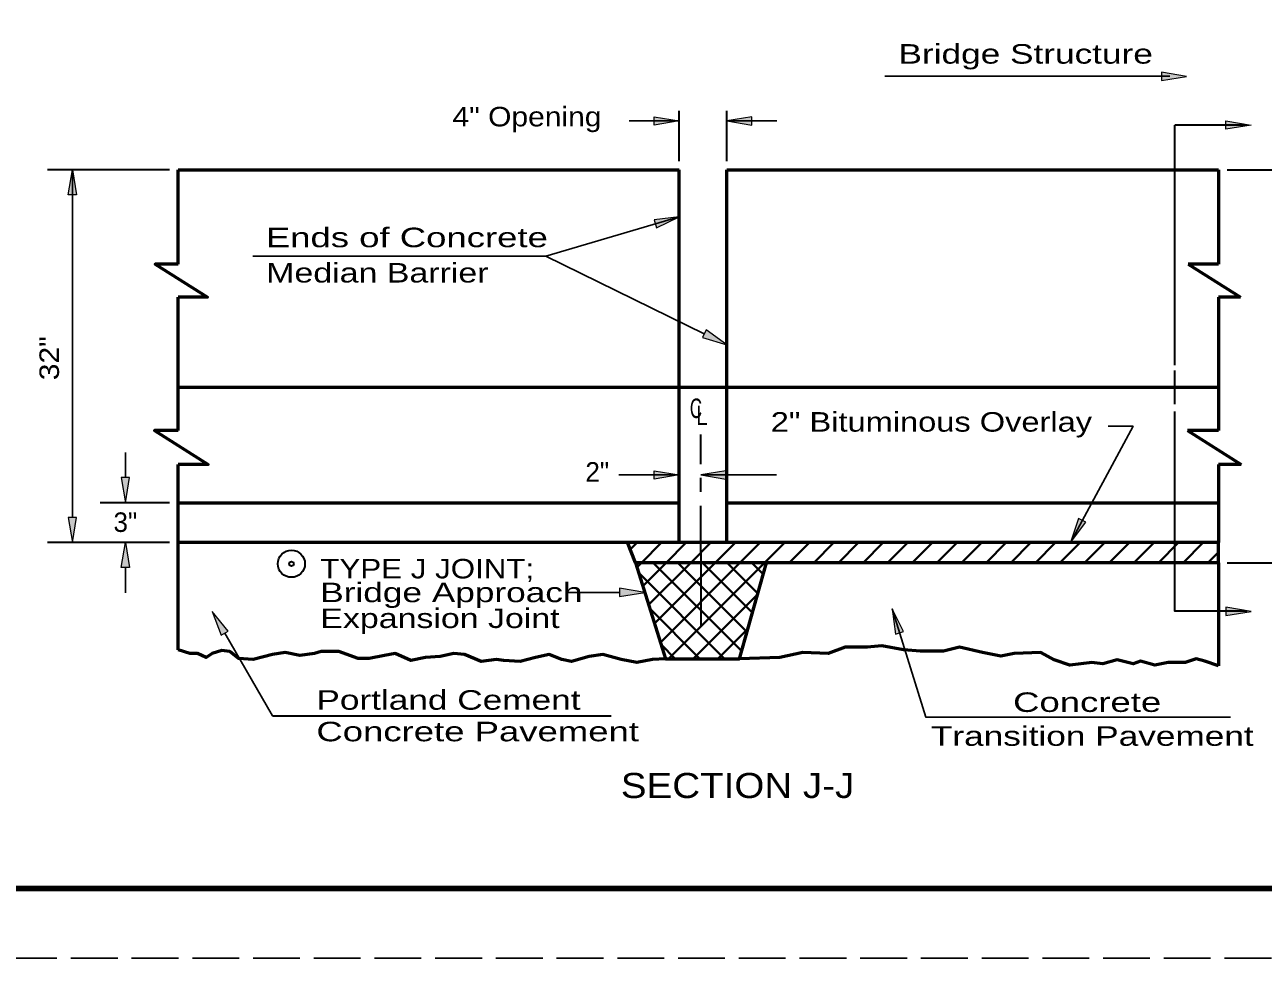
# Model space of a CAD drawing. Extents: x 14 to 49.3, y 28 to 50.
# Drawn here: x 31.51 to 40.4, y 28.04 to 34.74 of the extents above; entities that cross this region are included whole.
import ezdxf

# ---------------------------------------------------------------- set-up
doc = ezdxf.new("R2010")
doc.units = 0
doc.header["$LTSCALE"] = 0.056
doc.linetypes.add('LONG_DASH_SHORT_DASH', pattern=[9.9, 6, -1.2, 1.5, -1.2])
doc.linetypes.add('LONG_DASHED', pattern=[7.5, 6, -1.5])
for name, color, linetype, lineweight in [('1', 7, 'Continuous', 35), ('3', 7, 'Continuous', 13), ('5', 7, 'Continuous', 35), ('6', 7, 'Continuous', 13), ('7', 7, 'LONG_DASH_SHORT_DASH', 35)]:
    doc.layers.add(name, color=color, linetype=linetype, lineweight=lineweight)

msp = doc.modelspace()

# ---------------------------------------------------------------- hatches: boundary and pattern name
at = {"layer": '1'}
for points in [[(36.02508, 34.02208), (36.02508, 34.08208), (36.20508, 34.05208), (36.20508, 34.05208)], [(36.72583, 34.02208), (36.72583, 34.08208), (36.54583, 34.05208), (36.54583, 34.05208)], [(40.13058, 33.99175), (40.13058, 34.05175), (40.31058, 34.02175), (40.31058, 34.02175)], [(31.87767, 33.52033), (31.81767, 33.52033), (31.84767, 33.70033), (31.84767, 33.70033)], [(32.25767, 31.49233), (32.19767, 31.49233), (32.22767, 31.31233), (32.22767, 31.31233)], [(36.02508, 31.482), (36.02508, 31.542), (36.20508, 31.512), (36.20508, 31.512)], [(36.53942, 31.482), (36.53942, 31.542), (36.3595, 31.512), (36.3595, 31.512)], [(31.87767, 31.20633), (31.81767, 31.20633), (31.84767, 31.02633), (31.84767, 31.02633)], [(32.25767, 30.84633), (32.19767, 30.84633), (32.22767, 31.02633), (32.22767, 31.02633)], [(40.13058, 30.56192), (40.13058, 30.50192), (40.31058, 30.53192), (40.31058, 30.53192)]]:
    msp.add_hatch(color=256, dxfattribs=at).paths.add_polyline_path(points)
at = {"layer": '3'}
for points in [[(39.66742, 34.40083), (39.66742, 34.34083), (39.84742, 34.37083), (39.84742, 34.37083)], [(36.02392, 33.34167), (36.04075, 33.28408), (36.20508, 33.36342), (36.20508, 33.36342)], [(36.39725, 32.55167), (36.37092, 32.49775), (36.54583, 32.44575), (36.54583, 32.44575)], [(39.12492, 31.17192), (39.07175, 31.19975), (39.01492, 31.02633), (39.01492, 31.02633)], [(35.77675, 30.69825), (35.77675, 30.63825), (35.95675, 30.66825), (35.95675, 30.66825)], [(32.915, 30.361), (32.96692, 30.39108), (32.85067, 30.53175), (32.85067, 30.53175)], [(37.75733, 30.37017), (37.81458, 30.38775), (37.73308, 30.551), (37.73308, 30.551)]]:
    msp.add_hatch(color=256, dxfattribs=at).paths.add_polyline_path(points)

# ---------------------------------------------------------------- linework, layer by layer
at = {"layer": '1'}
for p, q in [((36.20508, 33.76283), (36.20508, 34.1235)), ((36.54583, 33.76283), (36.54583, 34.1235)), ((32.5445, 33.70033), (31.66767, 33.70033)), ((40.13825, 33.70033), (40.86358, 33.70033)), ((32.5445, 31.31233), (32.04767, 31.31233)), ((32.5445, 31.02633), (31.66767, 31.02633)), ((32.5445, 31.02633), (32.04767, 31.02633)), ((40.13825, 30.8815), (40.86358, 30.8815))]:
    msp.add_line(p, q, dxfattribs=at)
at = {"layer": '1', "lineweight": 25}
for p, q in [((36.20508, 34.05208), (35.84508, 34.05208)), ((36.54583, 34.05208), (36.90583, 34.05208)), ((31.84767, 31.20633), (31.84767, 33.70033)), ((32.22767, 31.49233), (32.22767, 31.67233)), ((36.20508, 31.512), (35.77208, 31.512)), ((36.90225, 31.512), (36.3595, 31.512)), ((32.22767, 30.84633), (32.22767, 30.66633))]:
    msp.add_line(p, q, dxfattribs=at)
at = {"layer": '1', "lineweight": 53}
for p, q in [((32.607, 33.70033), (36.20508, 33.70033)), ((32.607, 33.02375), (32.607, 33.70033)), ((36.20508, 31.02633), (36.20508, 33.70033)), ((36.54583, 31.02633), (36.54583, 33.70033)), ((36.54583, 33.70033), (40.07575, 33.70033)), ((40.07575, 33.70033), (40.07575, 33.02375)), ((39.8585, 33.02375), (40.23475, 32.78767)), ((40.07575, 33.02375), (39.8585, 33.02375)), ((32.607, 31.83108), (32.607, 32.78767)), ((40.23475, 32.78767), (40.07575, 32.78767)), ((40.07575, 32.78767), (40.07575, 31.83108)), ((32.607, 32.14167), (40.07575, 32.14167)), ((39.85458, 31.83108), (40.23858, 31.58683)), ((40.07575, 31.83108), (39.85458, 31.83108)), ((32.607, 30.25683), (32.607, 31.58683)), ((40.23858, 31.58683), (40.07575, 31.58683)), ((40.07575, 31.58683), (40.07575, 31.02633)), ((32.607, 31.31233), (36.20508, 31.31233)), ((36.54583, 31.31233), (40.07575, 31.31233)), ((35.83275, 31.02633), (32.607, 31.02633)), ((40.07575, 31.02633), (35.83275, 31.02633)), ((35.88975, 30.8815), (35.83275, 31.02633)), ((40.07575, 30.8815), (40.07575, 31.02633)), ((40.07575, 30.8815), (40.07575, 30.143))]:
    msp.add_line(p, q, dxfattribs=at)
at = {"layer": '1', "lineweight": 13}
msp.add_line((36.20508, 31.55558), (36.20508, 31.43808), dxfattribs=at)
at = {"layer": '1', "lineweight": 40}
for p, q in [((35.85217, 30.977), (35.90158, 31.02633)), ((35.9335, 30.8815), (36.07833, 31.02633)), ((36.11025, 30.8815), (36.25508, 31.02633)), ((36.287, 30.8815), (36.43192, 31.02633)), ((36.46383, 30.8815), (36.60867, 31.02633)), ((36.64058, 30.8815), (36.78542, 31.02633)), ((36.81733, 30.8815), (36.96225, 31.02633)), ((36.99417, 30.8815), (37.139, 31.02633)), ((37.17092, 30.8815), (37.31575, 31.02633)), ((37.34767, 30.8815), (37.49258, 31.02633)), ((37.5245, 30.8815), (37.66933, 31.02633)), ((37.70125, 30.8815), (37.84608, 31.02633)), ((37.878, 30.8815), (38.02292, 31.02633)), ((38.05475, 30.8815), (38.19967, 31.02633)), ((38.23158, 30.8815), (38.37642, 31.02633)), ((38.40833, 30.8815), (38.55325, 31.02633)), ((38.58508, 30.8815), (38.73, 31.02633)), ((38.76192, 30.8815), (38.90675, 31.02633)), ((38.93867, 30.8815), (39.08358, 31.02633)), ((39.11542, 30.8815), (39.26033, 31.02633)), ((39.29225, 30.8815), (39.43708, 31.02633)), ((39.469, 30.8815), (39.61392, 31.02633)), ((39.64575, 30.8815), (39.79067, 31.02633)), ((39.82258, 30.8815), (39.96742, 31.02633)), ((39.99933, 30.8815), (40.07575, 30.95792)), ((35.90025, 30.84825), (35.9335, 30.8815)), ((35.9425, 30.71375), (36.11025, 30.8815)), ((35.98475, 30.57925), (36.287, 30.8815)), ((36.65342, 30.24592), (36.01783, 30.8815)), ((36.027, 30.44475), (36.46383, 30.8815)), ((36.06925, 30.31017), (36.64058, 30.8815)), ((36.12875, 30.19292), (36.81733, 30.8815)), ((36.69192, 30.38417), (36.19458, 30.8815)), ((36.7305, 30.52233), (36.37133, 30.8815)), ((36.76908, 30.66058), (36.54817, 30.8815)), ((36.80758, 30.79875), (36.72492, 30.8815)), ((36.52958, 30.19292), (35.91208, 30.81042)), ((36.30558, 30.19292), (36.76742, 30.65483)), ((36.35283, 30.19292), (35.99308, 30.55267)), ((36.48233, 30.19292), (36.69908, 30.40967)), ((36.17608, 30.19292), (36.07408, 30.29483))]:
    msp.add_line(p, q, dxfattribs=at)
at = {"layer": '1', "linetype": 'LONG_DASHED', "lineweight": 25}
msp.add_line((49.17658, 28.04392), (13.97658, 28.04392), dxfattribs=at)
at = {"layer": '1', "lineweight": 158}
msp.add_lwpolyline([(49.09325, 49.54392), (49.09325, 28.54392), (16.59325, 28.54392)], dxfattribs=at)
at = {"layer": '1', "lineweight": 13}
for points in [[(36.02508, 34.02208), (36.02508, 34.08208), (36.20508, 34.05208), (36.20508, 34.05208)], [(36.72583, 34.02208), (36.72583, 34.08208), (36.54583, 34.05208), (36.54583, 34.05208)], [(40.13058, 33.99175), (40.13058, 34.05175), (40.31058, 34.02175), (40.31058, 34.02175)], [(31.87767, 33.52033), (31.81767, 33.52033), (31.84767, 33.70033), (31.84767, 33.70033)], [(32.25767, 31.49233), (32.19767, 31.49233), (32.22767, 31.31233), (32.22767, 31.31233)], [(36.02508, 31.482), (36.02508, 31.542), (36.20508, 31.512), (36.20508, 31.512)], [(36.53942, 31.482), (36.53942, 31.542), (36.3595, 31.512), (36.3595, 31.512)], [(31.87767, 31.20633), (31.81767, 31.20633), (31.84767, 31.02633), (31.84767, 31.02633)], [(32.25767, 30.84633), (32.19767, 30.84633), (32.22767, 31.02633), (32.22767, 31.02633)], [(40.13058, 30.56192), (40.13058, 30.50192), (40.31058, 30.53192), (40.31058, 30.53192)]]:
    msp.add_lwpolyline(points, close=True, dxfattribs=at)
at = {"layer": '1', "lineweight": 53}
for points in [[(32.607, 33.02375), (32.441, 33.02375), (32.81733, 32.78767), (32.607, 32.78767)], [(32.607, 31.83108), (32.43717, 31.83108), (32.82117, 31.58683), (32.607, 31.58683)], [(40.07575, 30.8815), (35.88975, 30.8815), (36.10617, 30.19292)], [(36.10617, 30.19292), (36.63858, 30.19292), (36.83067, 30.8815)], [(36.10617, 30.19292), (36.01275, 30.18692), (35.90083, 30.16492), (35.78892, 30.18692), (35.656, 30.22358), (35.55808, 30.20892), (35.43217, 30.17225), (35.36217, 30.18692), (35.27125, 30.22358), (35.17333, 30.20158), (35.06142, 30.17225), (34.94242, 30.17958), (34.8935, 30.18692), (34.78158, 30.17225), (34.66258, 30.22358), (34.58567, 30.23092), (34.48775, 30.20892), (34.38283, 30.20158), (34.27783, 30.17958), (34.16592, 30.23092), (34.089, 30.21625), (33.97708, 30.19425), (33.90008, 30.19425), (33.76017, 30.24558), (33.63425, 30.24558), (33.58525, 30.23092), (33.48033, 30.21625), (33.37542, 30.23825), (33.2845, 30.22358), (33.14458, 30.18692), (33.03958, 30.19408), (32.97667, 30.2455), (32.92067, 30.25283), (32.85067, 30.23083), (32.80875, 30.2015), (32.74575, 30.23083), (32.68983, 30.23083), (32.607, 30.25683)], [(40.07575, 30.143), (39.97775, 30.17467), (39.91667, 30.193), (39.83825, 30.1655), (39.71617, 30.1655), (39.62025, 30.14725), (39.51567, 30.17467), (39.46333, 30.15642), (39.35, 30.18383), (39.24542, 30.15642), (39.16692, 30.1655), (39.01, 30.14725), (38.89667, 30.18383), (38.80075, 30.23867), (38.609, 30.22958), (38.51308, 30.21125), (38.38225, 30.23867), (38.21667, 30.27525), (38.10333, 30.24783), (37.93767, 30.24783), (37.81558, 30.257), (37.65867, 30.28442), (37.55408, 30.27525), (37.39717, 30.27525), (37.27508, 30.22958), (37.092, 30.23867), (36.92633, 30.20208), (36.63858, 30.19292)]]:
    msp.add_lwpolyline(points, dxfattribs=at)
at = {"layer": '3', "lineweight": 25}
for p, q in [((39.72842, 34.37258), (37.68217, 34.37258)), ((36.38408, 32.52475), (35.246, 33.08067)), ((35.77675, 30.66825), (35.39017, 30.66825)), ((32.94092, 30.376), (33.28442, 29.78308))]:
    msp.add_line(p, q, dxfattribs=at)
at = {"layer": '3', "lineweight": 35}
for p, q in [((36.3595, 30.95392), (36.3595, 30.42508)), ((33.28442, 29.78308), (35.71683, 29.78308))]:
    msp.add_line(p, q, dxfattribs=at)
at = {"layer": '3'}
for points in [[(39.66742, 34.40083), (39.66742, 34.34083), (39.84742, 34.37083), (39.84742, 34.37083)], [(36.02392, 33.34167), (36.04075, 33.28408), (36.20508, 33.36342), (36.20508, 33.36342)], [(36.39725, 32.55167), (36.37092, 32.49775), (36.54583, 32.44575), (36.54583, 32.44575)], [(39.12492, 31.17192), (39.07175, 31.19975), (39.01492, 31.02633), (39.01492, 31.02633)], [(35.77675, 30.69825), (35.77675, 30.63825), (35.95675, 30.66825), (35.95675, 30.66825)], [(32.915, 30.361), (32.96692, 30.39108), (32.85067, 30.53175), (32.85067, 30.53175)], [(37.75733, 30.37017), (37.81458, 30.38775), (37.73308, 30.551), (37.73308, 30.551)]]:
    msp.add_lwpolyline(points, close=True, dxfattribs=at)
at = {"layer": '3', "lineweight": 25}
for points in [[(36.20508, 33.36342), (35.246, 33.08067), (33.14383, 33.08067)], [(39.01492, 31.02633), (39.46417, 31.8615), (39.28567, 31.8615)], [(37.73308, 30.551), (37.97475, 29.77417), (40.16408, 29.77417)]]:
    msp.add_lwpolyline(points, dxfattribs=at)
at = {"layer": '3', "lineweight": 35}
for radius in [0.09708, 0.01618]:
    msp.add_circle((33.42, 30.87408), radius, dxfattribs=at)
at = {"layer": '5'}
for p, q in [((40.28108, 34.021), (39.764, 34.021)), ((39.764, 32.29817), (39.764, 34.021)), ((39.764, 32.02008), (39.764, 32.26183))]:
    msp.add_line(p, q, dxfattribs=at)
msp.add_lwpolyline([(40.28108, 30.53367), (39.764, 30.53367), (39.764, 31.96725)], dxfattribs=at)
at = {"layer": '6'}
for p, q in [((36.20508, 33.9435), (36.20517, 33.9435)), ((31.84767, 33.70033), (31.84775, 33.70033)), ((32.607, 33.70033), (32.60708, 33.70033)), ((36.20508, 33.70033), (36.20517, 33.70033)), ((36.54583, 33.70033), (36.54592, 33.70033)), ((40.07575, 33.70033), (40.07583, 33.70033)), ((36.20508, 31.61808), (36.20517, 31.61808)), ((36.20508, 31.61808), (36.20517, 31.61808)), ((36.3595, 31.60342), (36.35958, 31.60342)), ((32.22767, 31.31233), (32.22775, 31.31233)), ((32.607, 31.31233), (32.60708, 31.31233)), ((32.607, 31.02633), (32.60708, 31.02633)), ((32.607, 31.02633), (32.60708, 31.02633)), ((40.07575, 30.8815), (40.07583, 30.8815))]:
    msp.add_line(p, q, dxfattribs=at)
at = {"layer": '7'}
msp.add_line((36.3595, 30.95392), (36.3595, 31.80167), dxfattribs=at)

# ---------------------------------------------------------------- texts
at = {"layer": '1', "width": 1.15}
msp.add_text('4" Opening', height=0.14, dxfattribs=at).set_placement((34.57633, 34.01267))
msp.add_text('32"', height=0.14, rotation=90.122, dxfattribs=at).set_placement((31.75092, 32.19125))
at = {"layer": '1'}
msp.add_text('2"', height=0.14, dxfattribs=at).set_placement((35.53075, 31.46358))
at = {"layer": '3'}
for s, height, width, p in [('Bridge Structure', 0.14, 1.35, (37.77942, 34.46283)), ('Ends of Concrete', 0.14, 1.4, (33.23633, 33.14575)), ('Median Barrier', 0.14, 1.3, (33.239, 32.89233)), ('C', 0.14, 0.65, (36.28083, 31.91975)), ('L', 0.14, 0.8, (36.326, 31.86883)), ('2" Bituminous Overlay', 0.14, 1.25, (36.86175, 31.82225)), ('TYPE J JOINT;', 0.14, 1.2, (33.62767, 30.76908)), ('Bridge Approach', 0.14, 1.35, (33.62717, 30.59875)), ('Expansion Joint', 0.14, 1.3, (33.62767, 30.41317)), ('Portland Cement', 0.14, 1.35, (33.59925, 29.82708)), ('Concrete', 0.14, 1.4, (38.60208, 29.81108)), ('Concrete Pavement', 0.14, 1.4, (33.59925, 29.60042)), ('Transition Pavement', 0.14, 1.35, (38.01167, 29.568)), ('SECTION J-J', 0.18, 1.15, (35.78533, 29.19325))]:
    msp.add_text(s, height=height, dxfattribs=dict(at, width=width)).set_placement(p)
msp.add_text('3"', height=0.14, dxfattribs=at).set_placement((32.14225, 31.10267))

doc.saveas('drawing.dxf')
